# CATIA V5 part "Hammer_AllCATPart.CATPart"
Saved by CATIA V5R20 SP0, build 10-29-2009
Part number: Hammer_AllCATPart
Bounding box of the stored display mesh (mm): x -31.1 to 31.1, y -255 to 0, z -25 to 425
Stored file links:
  C:\Users\Administrator\Desktop\临时\CATIA练习\Hammer_AllCATPart.CATPart
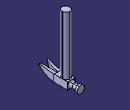
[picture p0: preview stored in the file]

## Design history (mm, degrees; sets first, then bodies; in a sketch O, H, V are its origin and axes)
Body1 "零件几何体" (main body)
  Solid1: solid without history
Body2 "几何体.2"
  Solid2 "实体.3": solid without history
